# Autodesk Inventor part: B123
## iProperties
Author: Administrator
Revision Number: A
Created: 2001-03
Part Number: B123
Document SubType Name: Modeling
Designer: Administrator
Description: BRACKET W/VERTICAL HOLES
Control State: 0
Master: False
Checked Out: False
PropertySet Name: Design Tracking Control
Shininess: 20.0
PropertySet Name: _Private Model Information
Density: 0.0
Volumn: 0.0
Area: 0.0
PropertySet Name: Model Information
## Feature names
1. Derived Body1 [Tagging]
